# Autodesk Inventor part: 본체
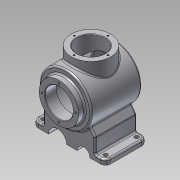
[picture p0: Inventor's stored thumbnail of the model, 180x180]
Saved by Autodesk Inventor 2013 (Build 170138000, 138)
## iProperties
Created: 2018-08
Part Number: 본체
Material: 알루미늄 6061
Document SubType Name: Modeling
Designer: hana-cad38
Density: 2.40731 g/cm^3
Mass: 1675.39 g
Surface Area: 1087.48 cm^2
Volume: 695.959 cm^3
Author: hana-cad38
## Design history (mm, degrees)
sketch "스케치1"
  geometry: L1 (-70, 40)-(70, 40); L2 (70, 40)-(70, -40); L3 (70, -40)-(-70, -40); L4 (-70, -40)-(-70, 40); L5 (-70, 40)-(70, -40); L6 (70, 40)-(-70, -40); 1 further point
  constraints: 12 end point, 2 midpoint, 2 parallel, 1 horizontal, 1 perpendicular
  dimensions: "d0" = 140 distance of L2.end L3.end; "d2" = 80 distance of L3.end L1.start
extrude "돌출1" new body sketch "스케치1" distance "d3" = 10; taper "d4" = 0 deg
sketch "스케치2"
  geometry: L1 (-60, 82)-(60, 82); L2 (-60, 82)-(-60, 120); L3 (-60, 120)-(-48, 120); L4 (-48, 120)-(-48, 132); L5 (-48, 132)-(48.671, 132); L6 (-40, 0)-(-40, 10) reference; L7 (40, 0)-(-40, 0) reference; A1 r 116 centre (-56, 82) between (60, 82) and (48.671, 132)
  constraints: 10 end point, 3 perpendicular, 3 point on circle, 2 point on line, 1 centre point, 1 horizontal, 1 parallel
  dimensions: "d5" = 116 radius of A1; "d6" = 120 distance of L1.start L1.end; "d7" = 12 distance of L2.end L3.end; "d8" = 76 diameter of L3 L1; "d9" = 100 diameter of L5 L1; "d116" = 8 distance between parallel lines of L6 L4; "d118" = 82 distance from line of L7 L1.start; "d142" = 108 distance from line of L1.end L4 (derived)
revolve "회전1" sketch "스케치2" stored, may be unused: angle "d14" = 90 deg
node "작업 평면1"
sketch "스케치4"
  geometry: L1 (-60, 44)-(-60, 120) reference; L2 (-60, 82)-(60, 82); L3 (-60, 109)-(-38, 109); L4 (-38, 109)-(-38, 119); L5 (-35, 122)-(40.125, 122); A1 r 116 centre (-56, 82) between (48.671, 32) and (48.671, 132) reference; A2 r 106 centre (-56, 82) between (50, 82) and (42.925, 120.078); A3 r 3 centre (-35, 119) between (-35, 122) and (-38, 119); A4 r 3 centre (40.125, 119) between (42.925, 120.078) and (40.125, 122); 3 further points
  constraints: 8 end point, 8 point on circle, 5 point on line, 4 tangent, 3 centre point, 2 parallel, 2 perpendicular, 1 equal radius, 1 midpoint
  dimensions: "d20" = 54 diameter of L3 L2; "d22" = 80 diameter of L5 L2; "d23" = 22 distance of L3.start L3.end; "d24" = 10 radial gap between concentric circles of A1 A2; "d97" = 3 radius of A3
revolve "회전2" sketch "스케치4" stored, may be unused: angle "d25" = 90 deg
node "작업 평면2"
sketch "스케치6"
  geometry: L1 (70, 10)-(-70, 10) reference; L2 (-50, 10)-(-50, 38.563); L3 (50, 10)-(50, 38.563); L4 (50, 38.563)-(40.304, 52.41); L5 (-50, 38.563)-(-40.304, 52.41); L6 (-50, 38.563)-(-70, 10); L7 (50, 38.563)-(70, 10); A1 r 50 centre (0, 82) between (40.304, 52.41) and (-40.304, 52.41) reference; 1 further point
  constraints: 12 end point, 2 collinear, 2 perpendicular, 2 point on circle, 2 point on line, 1 parallel
  dimensions: "d31" = 20 distance of L1.end L2.start; "d33" = 20 distance from line of L1.start L3; "d40" = 55 deg angle of L1 L4
extrude "돌출4" join sketch "스케치6" stored distance "d43" = 80; taper "d44" = 0 deg
sketch "스케치9"
  geometry: C1 r 27 at (0, 0) reference; 2 further points
  constraints: 1 vertical alignment
  dimensions: "d63" = 32.5 distance of point (0, 32.5) C1.centre
hole "구멍2" sketch "스케치9" at (0, 32.5) diameter "d64" = 3.242; stored, may be unused: countersink angle "d68" = 90 deg, drill point angle "d70" = 118 deg; dims "d65" = 8, "d66" = 4, "d67" = 2, "d69" = 10
node "작업 평면4"
  node "작업 평면3"
sketch "스케치11"
  geometry: C1 r 32.5 at (82, 0); 1 further point
  constraints: 1 centre point, 1 other
  dimensions: "d78" = 65 diameter of C1
feature "엠보싱1" sketch "스케치11" dims "d80" = 0.5, "d81" = 0
fillet "모깎기1" dims "d82" = 10
sketch "스케치12"
  geometry: A1 r 10 centre (-60, -30) between (-70, -30) and (-60, -40) reference; A2 r 10 centre (-60, 30) between (-60, 40) and (-70, 30) reference; 1 further point
hole "구멍3" sketch "스케치12" at (-60, 30), (-60, -30) diameter "d83" = 8; stored, may be unused: countersink angle "d87" = 90 deg, drill point angle "d89" = 0 deg; dims "d84" = 8, "d85" = 4, "d86" = 2, "d88" = 10
sketch "스케치13"
  geometry: A1 r 10 centre (60, 30) between (70, 30) and (60, 40) reference; A2 r 10 centre (60, -30) between (60, -40) and (70, -30) reference; 1 further point
hole "구멍4" sketch "스케치13" at (60, 30), (60, -30) diameter "d90" = 8; stored, may be unused: countersink angle "d94" = 90 deg, drill point angle "d96" = 0 deg; dims "d91" = 8, "d92" = 4, "d93" = 2, "d95" = 10
chamfer "모따기1" distance "d98" = 1; stored, may be unused: second distance "d99" = 2, angle "d100" = 45 deg
fillet "모깎기3" dims "d105" = 3
fillet "모깎기4" dims "d106" = 3
fillet "모깎기5" dims "d107" = 3
fillet "모깎기6" dims "d108" = 3
fillet "모깎기7" dims "d109" = 3
fillet "모깎기8" dims "d110" = 3
fillet "모깎기9" dims "d111" = 3
fillet "모깎기11" dims "d113" = 3
fillet "모깎기12" dims "d114" = 3
sketch "스케치14"
  geometry: L1 (47, -48)-(-47, -48) reference; C1 r 38 at (0, 2); 1 further point
  constraints: 1 centre point, 1 vertical alignment
  dimensions: "d119" = 50 distance from line of L1 C1.centre; "d134" = 76 diameter of C1
extrude "돌출6" join sketch "스케치14" stored distance "d120" = 10; taper "d121" = 0 deg
sketch "스케치15"
  geometry: C1 r 38 at (0, 0) reference; C2 r 27 at (0, 0); 1 further point
  constraints: 1 centre point, 1 coincident
  dimensions: "d122" = 54 diameter of C2
extrude "돌출7" cut sketch "스케치15" stored distance "d124" = 10; taper "d125" = 0 deg
sketch "스케치16"
  geometry: C1 r 27 at (0, 0) reference; 2 further points
  constraints: 1 vertical alignment
  dimensions: "d126" = 32.5 distance of point (0, 32.5) C1.centre
hole "구멍5" sketch "스케치16" at (0, 32.5) diameter "d127" = 3.242; stored, may be unused: countersink angle "d131" = 90 deg, drill point angle "d133" = 118 deg; dims "d128" = 8, "d129" = 4, "d130" = 2, "d132" = 10
chamfer "모따기3" distance "d138" = 1; stored, may be unused: second distance "d139" = 2, angle "d140" = 45 deg
fillet "모깎기13" dims "d141" = 3
sketch "스케치17"
  geometry: L1 (120, 0)-(0, 0) reference; C1 r 17.5 at (37.5, 0); C2 r 12.5 at (87.5, 0); 1 further point
  constraints: 2 centre point, 2 point on line
  dimensions: "d143" = 35 diameter of C1; "d145" = 25 diameter of C2; "d146" = 22.5 distance of point (60, 0) C1.centre; "d147" = 27.5 distance of point (60, 0) C2.centre
extrude "돌출8" cut sketch "스케치17" stored distance "d148" = 10; taper "d149" = 0 deg
node "솔리드1"
pattern_circular "원형 패턴2" dims angle "d72" = 360 deg
pattern_circular "원형 패턴3" dims angle "d136" = 360 deg
other parameters: "d15" = 147, "d30" = 90 deg, "d74" = 90 deg
